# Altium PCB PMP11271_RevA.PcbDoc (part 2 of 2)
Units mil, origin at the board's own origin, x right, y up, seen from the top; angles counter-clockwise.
Board outline 3600 x 2200 mil, 4 copper layers (Top Layer, Signal Layer 1, Signal Layer 2, Bottom Layer), stack 61.2 mil thick; 97 components, 68 nets, 279 pads, 71 vias.
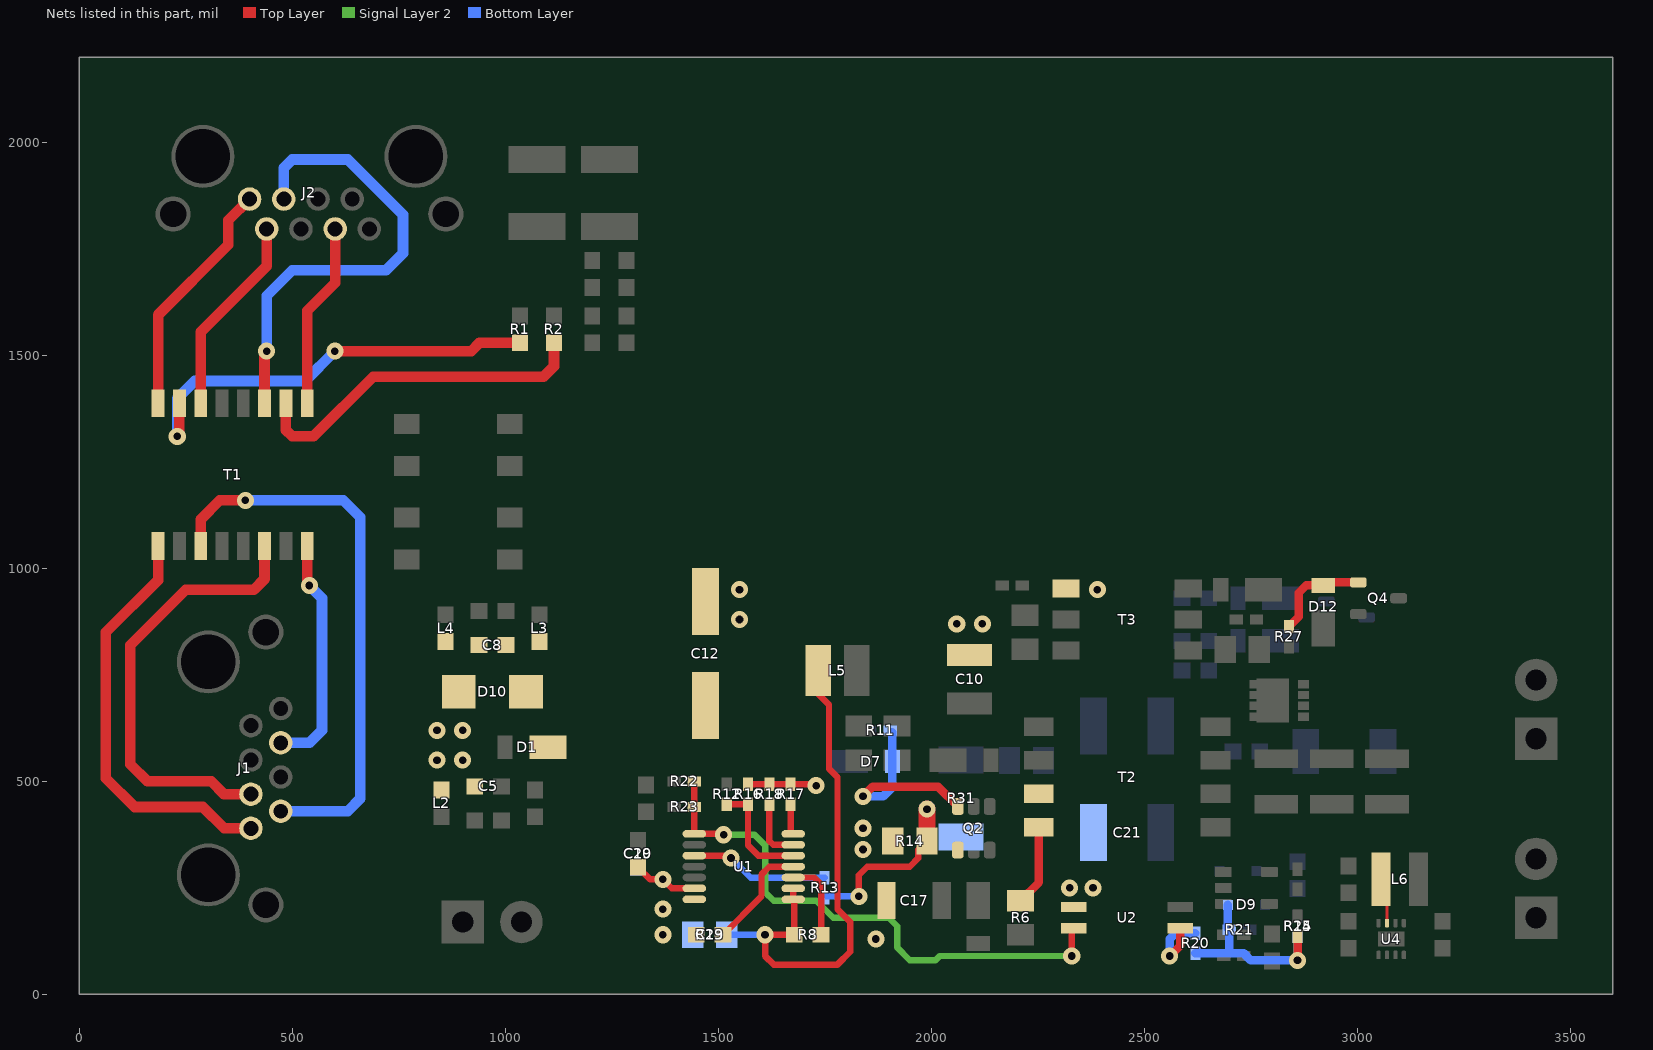
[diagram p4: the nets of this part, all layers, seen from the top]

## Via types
v1: diameter 40, hole 18, Top Layer to Bottom Layer, 69 vias
v2: diameter 19.68, hole 7.87, Top Layer to Bottom Layer, 2 vias

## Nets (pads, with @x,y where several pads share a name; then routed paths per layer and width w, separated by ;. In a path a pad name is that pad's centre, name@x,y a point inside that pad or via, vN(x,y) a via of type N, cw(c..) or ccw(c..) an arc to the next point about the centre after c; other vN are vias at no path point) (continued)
NetD7_2: D7.2 Q2.3 R11.2 | length 457.3
  Top Layer w20: v1(1840,465) 1862.44,487.44 2016.34,487.44 Q2.3@2062.6,441.18
  Bottom Layer w20: v1(1840,465) 1887.56,465 1908.72,486.16 D7.2@1908.72,546.71 R11.2@1908.72,614.9
NetD9_1: D9.1 R15.1 R20.2 R21.2 R24.2 | length 469.6
  Top Layer w20: v1(2860,80) R24.2@2860,136.38
  Bottom Layer w20: R20.2@2620,96.38 2733.62,96.38 2750,80 v1(2860,80) R15.1@2860,136.38 ; R21.2@2696.69,155.24 D9.1@2696.69,210 ; 2700.14,96.52 R21.2@2700.14,151.79
NetD12_2: D12.2 Q4.1 R27.1 | length 228.6
  Top Layer w20: R27.1@2840,863.62 2862.52,886.14 2862.52,942.52 2880.2,960.2 D12.2@2920,960.2 ; D12.2@2927.2,967.4 Q4.1@3002.76,967.4
NetJ1_1: J1.1 T1.1 | length 984.9
  Top Layer w25: T1.1@185.01,1052.49 185.01,972.51 62.5,850 62.5,507.5 130,440 290,440 340.16,389.84 J1.1@402.91,389.84
NetJ1_2: J1.2 T1.3 | length 1332.2
  Top Layer w25: T1.3@285.01,1052.49 285.01,1115.01 330,1160 v1(390,1160)
  Bottom Layer w25: v1(390,1160) 620,1160 660,1120 660,460 630,430 J1.2@472.99,430
NetJ1_3: J1.3 T1.6 | length 1048.5
  Top Layer w25: J1.3@402.91,470.16 339.84,470.16 310,500 160,500 120,540 120,820 250,950 410,950 435.01,975.01 T1.6@435.01,1052.49
NetJ1_6: J1.6 T1.8 | length 556.2
  Top Layer w25: T1.8@535.01,1052.49 535.01,964.99 v1(540,960)
  Bottom Layer w25: J1.6@472.99,590.63 540.63,590.63 570,620 570,930 v1(540,960)
NetJ2_1: J2.1 T1.16 | length 568.6
  Top Layer w25: T1.16@185.01,1387.49 185.01,1595.01 350,1760 350,1817.24 J2.1@399.84,1867.09
NetJ2_2: J2.2 T1.14 | length 473.7
  Top Layer w25: T1.14@285.01,1387.49 285.01,1555.01 440,1710 J2.2@440,1797.01
NetJ2_3: J2.3 T1.11 | length 1121
  Top Layer w25: T1.11@435.01,1387.49 435.01,1505.01 v1(440,1510)
  Bottom Layer w25: v1(440,1510) 440,1640 500,1700 720,1700 760,1740 760,1830 630,1960 500,1960 480.16,1940.16 J2.3@480.16,1867.09
NetJ2_6: J2.6 T1.9 | length 436.7
  Top Layer w25: T1.9@535.01,1387.49 535.01,1605.01 600.63,1670.63 J2.6@600.63,1797.01
NetL6_1: L6.1 U4.7 | length 88.7
  Top Layer w8: U4.7@3070.16,167.4 L6.1@3070.16,256.14
NetQ2_4: Q2.4 R13.1 R14.2 R31.1 | length 406.2
  Top Layer w15: v1(1830,230) 1830,280 1850,300 1950,300 1970,320 1970,340 R14.2@1990,360
  Top Layer w40: R14.2@1990,360 v1(1990,435)
  Bottom Layer w15: R13.1@1753.62,230 v1(1830,230)
NetR1_1: R1.1 T1.15 | length 1027
  Top Layer w25: v1(230,1310) 235.01,1315.01 T1.15@235.01,1387.49 ; v1(600,1510) 920,1510 939.68,1529.68 R1.1@1034.32,1529.68
  Bottom Layer w25: v1(230,1310) 230,1398.99 271.01,1440 530,1440 v1(600,1510)
NetR2_1: R2.1 T1.10 | length 821.4
  Top Layer w25: T1.10@485.01,1387.49 485.01,1324.99 500,1310 550,1310 690,1450 1090,1450 1114.32,1474.32 R2.1@1114.32,1529.68
NetR6_2: R6.2 T2.4 | length 189.6
  Top Layer w20: R6.2@2210,220 2252.72,262.72 T2.4@2252.72,391.89
NetR8_1: R8.1 U1.10 | length 190.4
  Top Layer w15: U1.10@1676.14,274.41 1725.59,274.41 1741.5,258.5 R8.1@1741.5,140
NetR12_1: R12.1 R16.2 U1.12 | length 262.6
  Top Layer w15: R12.1@1520,446.38 R16.2@1570,446.38 1570,350 1594.41,325.59 U1.12@1676.14,325.59
NetR13_2: R13.2 U1.3 | length 327.7
  Top Layer w15: U1.3@1443.86,325.59 1524.41,325.59 v1(1530,320)
  Bottom Layer w15: v1(1530,320) 1576.38,273.62 R13.2@1750,273.62
NetR17_2: R17.2 U1.14 | length 72.2
  Top Layer w15: R17.2@1670,446.38 1670,382.91 U1.14@1676.14,376.77
NetR18_2: R18.2 U1.13 | length 146.2
  Top Layer w15: R18.2@1620,446.38 1620,360 1628.82,351.18 U1.13@1676.14,351.18
NetR19_2: R19.2 U1.11 | length 261.1
  Top Layer w15: R19.2@1511.5,140 1601.5,230 1601.5,281.5 1620,300 U1.11@1676.14,300
NetR20_1: R20.1 U2.1 | length 181
  Top Layer w20: v1(2560,90) 2585,115 U2.1@2585,155
  Bottom Layer w20: v1(2560,90) 2560,130 2573.62,143.62 R20.1@2620,143.62
NetR22_1: R22.1 R23.1 U1.1 U2.4 | length 1297.3
  Top Layer w15: R22.1@1443.62,500 R23.1@1443.62,440 1443.86,439.76 U1.1@1443.86,376.77 1510.79,376.77 v1(1512.76,374.8) ; v1(2330,90) 2330,150 U2.4@2335,155
  Signal Layer 2 w15: v1(1512.76,374.8) 1585.2,374.8 1610,350 1610,240 1630,220 1730,220 1770,180 1900,180 1920,160 1920,110 1950,80 2010,80 2020,90 v1(2330,90)
PWRGND: C5.2 C10.2 C12.2 C17.2 C19.1 C20.2 C21.2 L2.2 R14.1 R16.1 R17.1 R18.1 T2.3 T3.4 U1.6 U2.3 | length 314.6
  Top Layer w15: C19.1@1311.32,298.5 1339.82,270 v1(1370,270) 1391.18,248.82 U1.6@1443.86,248.82 ; R16.1@1570,493.62 R18.1@1620,493.62 R17.1@1670,493.62 1726.38,493.62 v1(1730,490)
  other v1: 1870,130 2325,250 2380,250 1840,340 1840,390 840,550 900,550 2060,870 2120,870 1550,880 1550,950 2390,950
VDD: C8.1 C12.1 C23.1 D1.1 D10.1 L3.2 L5.1 R8.2 U1.8 U1.9 | length 1175.2
  Top Layer w15: U1.9@1676.14,248.82 U1.8@1676.14,223.23 1678.5,220.87 R8.2@1678.5,140 v1(1610,140) 1610,90 1630,70 1780,70 1810,100 1810,170 1780,200 1780,510 1760,530 1760,680 L5.1@1734.92,705.08
  Bottom Layer w15: C23.1@1520,140 v1(1610,140)
VSS: C8.2 C23.2 D10.2 L4.2 R19.1 U1.7
  other v1: 1370,140 1370,200 840,620 900,620
pads on no net: J2.4 J2.5 J2.7 J2.8 T1.4 T1.5 T1.12 T1.13 T3.2 T3.5 U3.1 U3.2 U4.4 U4.6

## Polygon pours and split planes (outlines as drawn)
5V on Top Layer "Top Layer-5V" (solid, remove dead copper, pour order 2): 2630,580 2630,520 3130,520 3130,580 3100,580
NetC16_1 on Top Layer "Top Layer-C16_1" (solid, remove dead copper, pour order 4): 2630,600 2840,600 2840,750 2630,750
NetC30_1 on Top Layer "Top Layer-C30_1" (solid, remove dead copper, pour order 6): 3140,150 3140,190 3120,190 3120,340 3230,340 3230,150
NetL6_1 on Top Layer "Top Layer-L6_1" (solid, remove dead copper, pour order 8): 3080,190 3030,190 3030,340 3080,340
NetC31_1 on Top Layer "Top Layer-D4_2" (solid, remove dead copper, pour order 10): 2290,520 2290,580 2120,580 2120,480 2090,480 2090,310 2180,310 2180,520
NetC9_2 on Top Layer "Top Layer-C9_2" (solid, remove dead copper, pour order 12): 2290,600 1790,600 1790,830 1970,830 1970,720 2290,720
NetQ2_4 on Top Layer "Top Layer-Q2_4" (solid, remove dead copper, pour order 16): 2070,310 1960,310 1960,400 2070,400
VDD on Top Layer "Top Layer-VDD" (solid, remove dead copper, pour order 20): 1200,540 1200,590 1770,590 1770,830 1650,830 1590,770 1340,770 1260,850 980,850 980,670 1008.9,641.1 1040,641.1 1040,540
NetC7_1 on Top Layer "Top Layer-C7_1" (solid, remove dead copper, pour order 22): 980,870 980,1050 1070,1050 1070,1210 980,1210 980,1270 1150,1270 1150,870
NetC7_2 on Top Layer "Top Layer-C7_2" (solid, remove dead copper, pour order 24): 960,870 960,1090 1050,1090 1050,1150 960,1150 960,1310 1050,1310 1050,1370 900,1370 840,1370 840,870
VSS on Top Layer "Top Layer-VSS" (solid, remove dead copper, pour order 26): 930,600 930,760 960,790 960,850 800,850 800,600
AUX on Top Layer "Top Layer-AUX" (solid, remove dead copper, pour order 28): 1100,460 970,460 970,620 1020,620 1020,520 1100,520
VSS on Top Layer "Top Layer-VSS" (solid, remove dead copper, pour order 30): 1470,100 1330,100 1330,230 1470,230
NetC1_1 on Top Layer "Top Layer-C1_1" (solid, remove dead copper, pour order 34): 1150,1840 1150,1570 1000,1570 1000,1840
NetC6_1 on Top Layer "Top Layer-C6_1" (solid, remove dead copper, pour order 40): 1170,1700 1170,1840 1320,1840 1320,1700
PWRGND on Top Layer "Top Layer-PWRGND" (solid, remove dead copper, pour order 52): 2415,50 2415,1050 1280,1050 1280,251 1489,251 1490,250 1490,50
GND on Top Layer "Top Layer-GND" (solid, remove dead copper, pour order 42): 2505,50 3550,50 3550,2150 1450,2150 1450,1150 2505,1150
EARTH on Top Layer "Top Layer-EARTH" (solid, remove dead copper, pour order 64): 1320,2140 1320,1930 910,1930 910,1550 720,1550 720,65 60,65 60,2140
PWRGND on Top Layer "Top Layer-PWRGND" (solid, remove dead copper, pour order 60): 950,460 950,570 800,570 800,460
NetC31_2 on Bottom Layer "Bottom Layer-C31_2" (solid, remove dead copper, pour order 37): 2210,490 1965,490 1965,590 2210,590
NetQ2_4 on Bottom Layer "Bottom Layer-Q2_4" (solid, remove dead copper, pour order 35): 1965,460 1965,325 2135,325 2135,460
NetC16_1 on Bottom Layer "Bottom Layer-C16_1" (solid, remove dead copper, pour order 33): 2730,505 2730,715 2655,715 2655,505
NetC16_2 on Bottom Layer "Bottom Layer-C16_2" (solid, remove dead copper, pour order 31): 2940,505 2940,635 2783.22,635 2750,635 2750,505
VSS on Bottom Layer "Bottom Layer-VSS" (solid, remove dead copper, pour order 32): 1470,230 1470,100 1160,100 1160,600 800,600 800,660 1260,660 1260,230
PWRGND on Bottom Layer "Bottom Layer-PWRGND" (solid, remove dead copper, pour order 54): 2415,50 1490,50 1490,250 1280,250 1280,460 800,460 800,850 1280,850 1280,1050 2415,1050
GND on Bottom Layer "Bottom Layer-GND" (solid, remove dead copper, pour order 50): 3550,50 2505,50 2505,1150 1450,1150 1450,2150 3550,2150
EARTH on Bottom Layer "Bottom Layer-EARTH" (solid, remove dead copper, pour order 62): 1320,2140 60,2140 60,60 65,65 720,65 720,1550 910,1550 910,1930 1320,1930
PWRGND on Signal Layer 1 "Signal Layer 1-PWRGND" (solid, remove dead copper, pour order 58): 2415,50 1490,50 1490,250 1280,250 1280,460 800,460 800,850 1280,850 1280,1050 2415,1050
GND on Signal Layer 1 "Signal Layer 1-GND" (solid, remove dead copper, pour order 44): 3550,50 2505,50 2505,1150 1450,1150 1450,2150 3550,2150
EARTH on Signal Layer 1 "Signal Layer 1-EARTH" (solid, remove dead copper, pour order 66): 1320,2140 1320,1930 910,1930 910,1550 720,1550 720,65 60,65 60,2140
PWRGND on Signal Layer 2 "Signal Layer 2-PWRGND" (solid, remove dead copper, pour order 56): 1280,1050 1280,850 800,850 800,460 1280,460 1280,250 1490,250 1490,50 2415,50 2415,1050
GND on Signal Layer 2 "Signal Layer 2-GND" (solid, remove dead copper, pour order 48): 3550,50 2505,50 2505,1150 1450,1150 1450,2150 3550,2150
EARTH on Signal Layer 2 "Signal Layer 2-EARTH" (solid, remove dead copper, pour order 68): 1320,2140 1320,1930 910,1930 910,1550 720,1550 720,65 60,65 60,2140

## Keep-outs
Keep-Out Layer:
  lines w8: -4,0 ccw(c0,0) 0,-4 ; -4,0 ccw(c0,0) 0,-4 ; -4,0 -4,2200 ; -4,2200 cw(c0,2200) 0,2204 ; -4,2200 cw(c0,2200) 0,2204 ; 0,-4 3600,-4 ; 0,2204 3600,2204 ; 3600,-4 ccw(c3600,0) 3604,0 ; 3600,-4 ccw(c3600,0) 3604,0 ; 3600,2204 cw(c3600,2200) 3604,2200 ; 3600,2204 cw(c3600,2200) 3604,2200 ; 3604,0 3604,2200
  text ".Layer_Name" at 577,-858.49 h60

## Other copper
Top Layer:
  text ".Layer_Name" at 577,-858.49 h60
Bottom Layer:
  text ".Layer_Name" at 577,-858.49 h60

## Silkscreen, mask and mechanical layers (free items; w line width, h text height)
Top Overlay:
  lines w10: 2620,72 2620,125.93 2634.07,140 2645,140 ; 2840,40 2875,40 ; 2985,65 3005,45 ; 2985,345 2995,355 3130,355 3135,360
  text ".PRJ_Number" at 2865,2050 h60
  text ".PCB_Rev" at 3465,2050 h60
  text ".Layer_Name" at 577,-858.49 h60
Bottom Overlay:
  text ".Layer_Name" at 577,-858.49 h60
Top Paste:
  text ".Layer_Name" at 577,-858.49 h60
Bottom Paste:
  text ".Layer_Name" at 577,-858.49 h60
Top Solder:
  text ".Layer_Name" at 577,-858.49 h60
  text ".Layer_Name" at 577,-858.49 h60
Bottom Solder:
  text ".Layer_Name" at 577,-858.49 h60
Drill Guide:
  text ".Layer_Name" at 577,-858.49 h60
M1 Board Outline:
  the board outline again, w10
  text ".Layer_Name" at 577,-858.49 h60
M2 Board Dimensions:
  rectangle: 0,-275 125,-150
  rectangle: 125,-400 500,-275
  lines w7: 0,-275 1000,-275 ; 125,-400 125,-150 ; 250,-400 250,-150 ; 500,-400 500,-150 ; 750,-400 750,-150 ; 0,-400 1000,-400 1000,-150 0,-150 0,-400
  text ".Layer_Name" at 577,-858.49 h60
M3 3D STEP Top:
  text ".Layer_Name" at 577,-858.49 h60
M4 3D STEP Bottom:
  text ".Layer_Name" at 577,-858.49 h60
M5 Assembly Top:
  lines w10: -292,-930.17 6308,-930.17 ; -292,-726.83 6310,-726.83 ; -292,-523.5 -292,-1133.5 3713,-1133.5 6310,-1133.5 6310,-523.5 -291.5,-523.5 -291.5,-1133.5 1284,-1133.5 ; 2173,-1133.5 2173,-523.5 ; 3440,-726.83 3440,-523.5 ; 4280,-726.83 4280,-523.5 ; 4902,-1140 4902,-937.17
  text "COMPONENTS MARKED 'DNP' SHOULD NOT BE POPULATED." at 1153.5,-318.5 h60
  text "ASSEMBLY VARIANT:" at 1153,-434 h60
  text ".VariantName" at 2189,-434 h60
  text "PCB VIEWED FROM TOP SIDE" at -228.5,-655.67 h60
  text "BOARD #:" at 2248,-655.67 h60
  text ".PRJ_Number" at 2793.5,-655.67 h60
  text "REV:" at 3638,-655.67 h60
  text ".PCB_Rev" at 3929.5,-655.67 h60
  text "SVN REV:" at 4476,-655.67 h60
  text ".VersionControl_RevNumber" at 4982,-655.67 h60
  text "TID #:" at 2248,-859 h60
  text ".TID" at 2793.5,-859 h60
  text "PLOT NAME =" at -228.5,-1064.34 h60
  text ".plot_File_Name" at 577,-1064.34 h60
  text "GENERATED    :" at 2250,-1064.34 h60
  text ".Print_Date" at 3119.5,-1064.34 h60
  text ".Print_Time" at 3848.5,-1064.34 h60
  text "TEXAS INSTRUMENTS" at 5113,-1064.34 h60
M6 Assembly Bottom:
  lines w10: -292.5,-727.33 6309.5,-727.33 ; -290.5,-930.67 6309.5,-930.67 ; 1115.5,-1140.5 1115.5,-937.67 ; 1737.5,-727.33 1737.5,-524 ; 2577.5,-727.33 2577.5,-524 ; 3844.5,-1134 3844.5,-524 ; 4733.5,-1134 6309,-1134 6309,-524 -292.5,-524 -292.5,-1134 2304.5,-1134 6309.5,-1134 6309.5,-524
  text "COMPONENTS MARKED 'DNP' SHOULD NOT BE POPULATED." at 6102,-318 h60
  text ".VariantName" at 5058,-434 h60
  text "ASSEMBLY VARIANT:" at 6097,-434 h60
  text ".VersionControl_RevNumber" at 1035.5,-656.17 h60
  text "SVN REV:" at 1541.5,-656.17 h60
  text ".PCB_Rev" at 2088,-656.17 h60
  text "REV:" at 2379.5,-656.17 h60
  text ".PRJ_Number" at 3224,-656.17 h60
  text "BOARD #:" at 3769.5,-656.17 h60
  text "PCB VIEWED FROM BOTTOM SIDE" at 6246,-656.17 h60
  text ".TID" at 3224,-859.5 h60
  text "TID #:" at 3769.5,-859.5 h60
  text "TEXAS INSTRUMENTS" at 904.5,-1064.84 h60
  text ".Print_Time" at 2169,-1064.84 h60
  text ".Print_Date" at 2898,-1064.84 h60
  text "GENERATED    :" at 3767.5,-1064.84 h60
  text ".plot_File_Name" at 5440.5,-1064.84 h60
  text "PLOT NAME =" at 6246,-1064.84 h60
M9 Title Sheet:
  drawing of 57 lines, arcs and shapes, not listed
  text "1" at 739.84,8036.5 h70
  text "2" at 3235.5,8036.5 h70
  text "3" at 5724.84,8036.5 h70
  text "4" at 8231.51,8036.5 h70
  text "5" at 10730.5,8036.5 h70
  text "6" at 13235.5,8036.5 h70
  text "A" at -416.5,6893.5 h70
  text "A" at 14383.5,6893.5 h70
  text "B" at -416.5,4513.5 h70
  text "B" at 14383.5,4513.5 h70
  text "C" at -416.5,2138.5 h70
  text "C" at 14383.5,2138.5 h70
  text "PROJECT TITLE:" at 11343.5,277.5 h45
  text ".PRJ_Title" at 11393.5,144.17 h70
  text "DESIGNED FOR:" at 11343.5,-23.5 h45
  text ".PRJ_Customer" at 11393.5,-163.5 h70
  text "D" at -416.5,-231.5 h70
  text "D" at 14383.5,-231.5 h70
  text "FILE NAME:" at 11343.5,-323.5 h45
  text ".PCB_File_Name_No_Path" at 11393.5,-443.5 h70
  text "Texas Instruments (TI) and/or its licensors do not warrant the accuracy or completeness of this specification" at 6374,-605.34 h45
  text "ENGINEER:" at 11343.5,-613.5 h45
  text "LAYOUT BY:" at 12848.5,-613.5 h45
  text "or any information contained therein. TI and/or its licensors do not warrant that this design will meet" at 6329.01,-718 h45
  text ".PRJ_Engineer" at 11393.5,-768.49 h70
  text ".PCB_Layout" at 12899,-768.49 h70
  text "the specifications, will be suitable for your application or fit for any particular purpose, or will operate in" at 6329.01,-830.67 h45
  text ".Layer_Name" at 577,-858.49 h60
  text "ALTIUM DESIGNER VERSION:" at 12848.5,-923.5 h45
  text "an implementation. TI and/or its licensors do not warrant that the design is production worthy. You should" at 6329.01,-943.33 h45
  text "completely validate and test your design implementation to confirm the system functionality for your application." at 6374,-1056 h45
  text ".print_Scale" at 11393.5,-1056.83 h70
  text ".Application_BuildNumber" at 12899,-1056.83 h70
  text "1" at 739.84,-1263.5 h70
  text "2" at 3235.5,-1263.5 h70
  text "3" at 5724.84,-1263.5 h70
  text "4" at 8231.51,-1263.5 h70
  text "5" at 10730.5,-1263.5 h70
  text "6" at 13235.5,-1263.5 h70
M10 Fab Notes:
  drawing of 185 lines, arcs and shapes, not listed
  text "DESIGN INFORMATION" at 12381.02,5910 h60
  text "MIN. TRACK WIDTH:" at 11736.46,5730 h60
  text "8" at 12832.7,5730 h60
  text "MIL" at 12987.46,5730 h60
  text "MIN. CLEARANCE:" at 11736.46,5598 h60
  text "0.2" at 12772.7,5598 h60
  text "mm" at 12987.46,5598 h60
  text "MIN. VIA PAD SIZE:" at 11736.46,5466 h60
  text "24" at 12802.71,5466 h60
  text "MIL" at 12987.46,5466 h60
  text "0.05mm (2MIL)" at 12431.46,5324.29 h60
  text "MINIMUM ANNULAR RING" at 11407.23,5320 h60
  text "EXTERNAL" at 13139.46,5320 h60
  text "PER" at 11607.23,5202 h60
  text "IPC-D-275 CLASS 2 LEVEL C" at 11827.23,5202 h60
  text "MIL, HOLES" at 13315.46,5089.71 h60
  text "+/-" at 12923,5089 h60
  text "+/-" at 13777,5089 h60
  text "REGISTRATION TOLERANCES:" at 11407.23,5084 h60
  text "METAL" at 12607,5084 h60
  text "5" at 13183.2,5084 h60
  text "3" at 14016.2,5084 h60
  text "MIL" at 14132.46,5084 h60
  text "MATERIAL:" at 11332.46,4874.54 h60
  text "FR-4 High Tg" at 12318.9,4734.21 h60
  text "FR-408" at 11753.46,4725.64 h60
  text "X" at 12165.46,4725.64 h60
  text "OTHER" at 13241.46,4725.64 h60
  text "62 MIL (1.6mm) +/-10%" at 12073.56,4562.92 h60
  text "THICKNESS:" at 11407.23,4558.64 h60
  text "X" at 11945.4,4558.64 h60
  text "OTHER" at 13358.46,4558.64 h60
  text "TOLERANCE:" at 11407.23,4400.64 h60
  text "X" at 12246.53,4400.64 h60
  text "ANSI IPC-6012 TYPE 3 CLASS 2" at 12433.48,4400.64 h60
  text "OTHER +/-" at 12433.46,4244.64 h60
  text "BOW & TWIST:" at 11407.23,4087.64 h60
  text "X" at 12246.53,4087.64 h60
  text "ANSI IPC-6012 TYPE 3 CLASS 2" at 12433.48,4087.64 h60
  text "OTHER +/-" at 12433.46,3929.13 h60
  text "DRILLING:" at 11332.46,3790.64 h60
  text "REFERENCE:" at 11407.23,3673.64 h60
  text "X" at 12055.46,3673.64 h60
  text "AS SHOWN" at 12242.46,3673.64 h60
  text "X" at 12956.46,3673.64 h60
  text "NC_DRILL FILES" at 13093.46,3673.64 h60
  text "PTH MIN COPPER THICKNESS:" at 11407.23,3515.64 h60
  text "X" at 12757.46,3515.64 h60
  text "1MIL" at 12894.46,3515.64 h60
  text "OTHER" at 13391.46,3515.64 h60
  text "BOARD FINISH:" at 11332.46,3356.64 h60
  text "SILKSCREEN:" at 11487.68,3238.64 h60
  text "X" at 12436.46,3238.64 h60
  text "TOP" at 12562.46,3238.64 h60
  text "X" at 12946.46,3238.64 h60
  text "BOTTOM" at 13073.46,3238.64 h60
  text "SILKSCREEN COLOR:" at 11487.68,3071.64 h60
  text "X" at 12435.42,3071.64 h60
  text "WHITE" at 12562.46,3071.64 h60
  text "OTHER" at 13073.46,3071.64 h60
  text "SOLDER RESIST COLOR:" at 11487.68,2901.64 h60
  text "X" at 12055.42,2742.44 h60
  text "GREEN" at 12182.46,2742.44 h60
  text "BLUE" at 12773.46,2742.44 h60
  text "OTHER" at 13311.46,2742.44 h60
  text "IMMERSION GOLD (ENIG)" at 12393.46,2553.92 h60
  text "ENEPIG" at 13731,2550.64 h60
  text "SURFACE FINISH:" at 11332.46,2549.64 h60
  text "IMM. TIN/SILVER OR EQUIV" at 11662,2392.64 h60
  text "OTHER" at 13093.46,2392.64 h60
  text "X" at 11495,2390 h60
  text "X" at 12200,2215 h60
  text "ARRAY/PANEL:" at 11332.46,2213.64 h60
  text "CUT AND TRIM PER MECH LAYER 1" at 12393.46,2209.35 h60
  text "N.C. ROUTE" at 12393.46,2057.64 h60
  text "V. SCORE" at 13259.46,2057.64 h60
  text "CERTIFICATION:" at 11332.46,1920.64 h60
  text "MATERIALS AND WORKMANSHIP FOR ALL PCBS" at 12057.46,1920.64 h60
  text "TO MEET OR EXCEED THE REQUIREMENTS OF:" at 12057.46,1822.64 h60
  text "X" at 11683.96,1686.13 h60
  text "ANSI IPC-A-600F CLASS ->" at 11822.96,1686.13 h60
  text "X" at 13462.02,1686.13 h60
  text "2" at 13580.96,1686.14 h60
  text "1" at 13265.96,1684.64 h60
  text "3" at 13934.96,1684.64 h60
  text "X" at 11686.02,1526.64 h60
  text "UL 94V-0" at 11822.96,1526.64 h60
  text "X" at 12498.02,1526.64 h60
  text "RoHS" at 12634.96,1526.64 h60
  text "OTHER" at 13279.36,1526.64 h60
  text "PER ORDER" at 13676.42,1526.64 h60
  text "ADDITIONAL REQUIREMENTS:" at 11332.46,1385.64 h60
  text "MICROSECTION:" at 11407.23,1270.64 h60
  text "YES" at 12312.96,1270.64 h60
  text "REQUIRED" at 13174.46,1114.49 h60
  text "BARE BOARD ELEC. TEST:" at 11407.23,1111.64 h60
  text "NONE" at 12712.96,1111.64 h60
  text "X" at 13047.46,1111.64 h60
  text "PER ORDER" at 13766.46,1111.64 h60
  text "MANUFACTURER'S UL:" at 11407.23,954.64 h60
  text "RAIL" at 12572.96,950.35 h60
  text "METAL" at 13064.77,950.35 h60
  text "X" at 13440,950 h60
  text "SILK" at 13576.46,950.35 h60
  text ".Layer_Name" at 577,-858.49 h60
M11 Gerber Information:
  lines w10: -292,-930.17 6308,-930.17 ; -292,-726.83 6310,-726.83 ; -292,-523.5 -292,-1133.5 3713,-1133.5 6310,-1133.5 6310,-523.5 -291.5,-523.5 -291.5,-1133.5 1284,-1133.5 ; 2173,-1133.5 2173,-523.5 ; 3440,-726.83 3440,-523.5 ; 4280,-726.83 4280,-523.5 ; 4902,-1140 4902,-937.17
  text "ALL ARTWORK VIEWED FROM TOP SIDE" at -228.5,-655.67 h60
  text "BOARD #:" at 2248,-655.67 h60
  text ".PRJ_Number" at 2793.5,-655.67 h60
  text "REV:" at 3638,-655.67 h60
  text ".PCB_Rev" at 3929.5,-655.67 h60
  text "SVN REV:" at 4476,-655.67 h60
  text ".VersionControl_RevNumber" at 4982,-655.67 h60
  text "LAYER NAME =" at -228.5,-858.49 h60
  text "TID #:" at 2248,-859 h60
  text ".TID" at 2793.5,-859 h60
  text "PLOT NAME =" at -228.5,-1064.34 h60
  text ".plot_File_Name" at 577,-1064.34 h60
  text "GENERATED    :" at 2250,-1064.34 h60
  text ".Print_Date" at 3119.5,-1064.34 h60
  text ".Print_Time" at 3848.5,-1064.34 h60
  text "TEXAS INSTRUMENTS" at 5113,-1064.34 h60
M12 Stackup:
  drawing of 295 lines, arcs and shapes, not listed
  text "Layer" at 9580.35,7635 h60
  text "Name" at 9990.26,7635 h60
  text "Material" at 10930,7635 h60
  text "Thickness" at 11789.77,7635 h60
  text "Constant" at 12439.6,7635 h60
  text "Board Layer Stack" at 13009.46,7635 h60
  text "1" at 9580.35,7515 h60
  text "Top Overlay" at 9990.26,7515 h60
  text "2" at 9580.35,7395 h60
  text "Top Solder" at 9990.26,7395 h60
  text "Solder Resist" at 10930,7395 h60
  text "0.40mil" at 11789.77,7395 h60
  text "3.5" at 12439.6,7395 h60
  text "3" at 9580.35,7275 h60
  text "Top Layer" at 9990.26,7275 h60
  text "Copper" at 10930,7275 h60
  text "2.80mil" at 11789.77,7275 h60
  text "4" at 9580.35,7155 h60
  text "Dielectric1" at 9990.26,7155 h60
  text "FR-4" at 10930,7155 h60
  text "15.00mil" at 11789.77,7155 h60
  text "4.8" at 12439.6,7155 h60
  text "5" at 9580.35,7035 h60
  text "Signal Layer 1" at 9990.26,7035 h60
  text "Copper" at 10930,7035 h60
  text "2.80mil" at 11789.77,7035 h60
  text "6" at 9580.35,6915 h60
  text "Dielectric 3" at 9990.26,6915 h60
  text "20.00mil" at 11789.77,6915 h60
  text "4.2" at 12439.6,6915 h60
  text "7" at 9580.35,6795 h60
  text "Signal Layer 2" at 9990.26,6795 h60
  text "Copper" at 10930,6795 h60
  text "2.80mil" at 11789.77,6795 h60
  text "8" at 9580.35,6675 h60
  text "Dielectric 2" at 9990.26,6675 h60
  text "15.00mil" at 11789.77,6675 h60
  text "4.2" at 12439.6,6675 h60
  text "9" at 9580.35,6555 h60
  text "Bottom Layer" at 9990.26,6555 h60
  text "Copper" at 10930,6555 h60
  text "2.80mil" at 11789.77,6555 h60
  text "10" at 9580.35,6435 h60
  text "Bottom Solder" at 9990.26,6435 h60
  text "Solder Resist" at 10930,6435 h60
  text "0.40mil" at 11789.77,6435 h60
  text "3.5" at 12439.6,6435 h60
  text "11" at 9580.35,6315 h60
  text "Bottom Overlay" at 9990.26,6315 h60
  text ".Layer_Name" at 577,-858.49 h60
M13 Component Bodies Top:
  text ".Layer_Name" at 577,-858.49 h60
M14 Component Bodies Bottom:
  text ".Layer_Name" at 577,-858.49 h60
M15 Courtyards Top:
  text ".Layer_Name" at 577,-858.49 h60
M16 Courtyards Bottom:
  text ".Layer_Name" at 577,-858.49 h60
Drill Drawing:
  circle w1: c3917.72,976.04 r24.89
  lines w1: 3892.83,217 3905.27,217 3905.27,204.56 3930.16,204.56 3930.16,217 3942.6,217 3942.6,241.89 3930.16,241.89 3930.16,254.33 3905.27,254.33 3905.27,241.89 3892.83,241.89 3892.83,217 ; 3892.83,353.88 3917.72,366.32 3942.6,353.88 3930.16,378.76 3942.6,403.65 3917.72,391.21 3892.83,403.65 3905.27,378.76 3892.83,353.88 ; 3892.83,515.64 3905.27,515.64 3917.72,503.2 3930.16,515.64 3942.6,515.64 3930.16,528.08 3942.6,540.53 3930.16,540.53 3917.72,552.97 3905.27,540.53 3892.83,540.53 3905.27,528.08 3892.83,515.64 ; 3892.83,702.29 3942.6,702.29 3917.72,652.52 3892.83,702.29 ; 3892.83,801.84 3892.83,814.28 3905.27,826.72 3892.83,839.17 3892.83,851.61 3905.27,851.61 3917.72,839.17 3930.16,851.61 3942.6,851.61 3942.6,839.17 3930.16,826.72 3942.6,814.28 3942.6,801.84 3930.16,801.84 3917.72,814.28 3905.27,801.84 3892.83,801.84
  lines w12: 3825,159.76 5943.02,159.76 ; 3825,1055.68 5943.02,1055.68 ; 4195.36,10.44 4195.36,1205 ; 4552.36,10.44 4552.36,1205 ; 5213.93,10.44 5213.93,1205 ; 5498.07,10.44 5498.07,1205 ; 3825,10.44 5943.02,10.44 5943.02,1205 3825,1205 3825,10.44
  text "Symbol" at 3914.59,1100.48 h72
  text "Quantity" at 4240.16,1100.48 h72
  text "Finished Hole Size" at 4597.16,1100.48 h72
  text "Plated" at 5258.72,1100.48 h72
  text "Hole Type" at 5542.86,1100.48 h72
  text "2" at 4240.16,951.16 h60
  text "7.87mil (0.200mm)" at 4597.16,951.16 h60
  text "PTH" at 5258.72,951.16 h60
  text "Round" at 5542.86,951.16 h60
  text "69" at 4240.16,801.84 h60
  text "18.00mil (0.457mm)" at 4597.16,801.84 h60
  text "PTH" at 5258.72,801.84 h60
  text "Round" at 5542.86,801.84 h60
  text "16" at 4240.16,652.52 h60
  text "35.04mil (0.890mm)" at 4597.16,652.52 h60
  text "PTH" at 5258.72,652.52 h60
  text "Round" at 5542.86,652.52 h60
  text "6" at 4240.16,503.2 h60
  text "50.00mil (1.270mm)" at 4597.16,503.2 h60
  text "PTH" at 5258.72,503.2 h60
  text "Round" at 5542.86,503.2 h60
  text "4" at 4240.16,353.88 h60
  text "61.81mil (1.570mm)" at 4597.16,353.88 h60
  text "PTH" at 5258.72,353.88 h60
  text "Round" at 5542.86,353.88 h60
  text "4" at 4240.16,204.56 h60
  text "128.00mil (3.251mm)" at 4597.16,204.56 h60
  text "PTH" at 5258.72,204.56 h60
  text "Round" at 5542.86,204.56 h60
  text "101 Total" at 4240.16,55.24 h60
  text ".Layer_Name" at 577,-858.49 h60

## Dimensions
0,-400 to 1000,-400 on M2 Board Dimensions
0,0 to 0,2200 on M2 Board Dimensions
0,0 to 3600,0 on M2 Board Dimensions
